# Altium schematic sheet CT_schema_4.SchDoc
size 398 x 262 mm
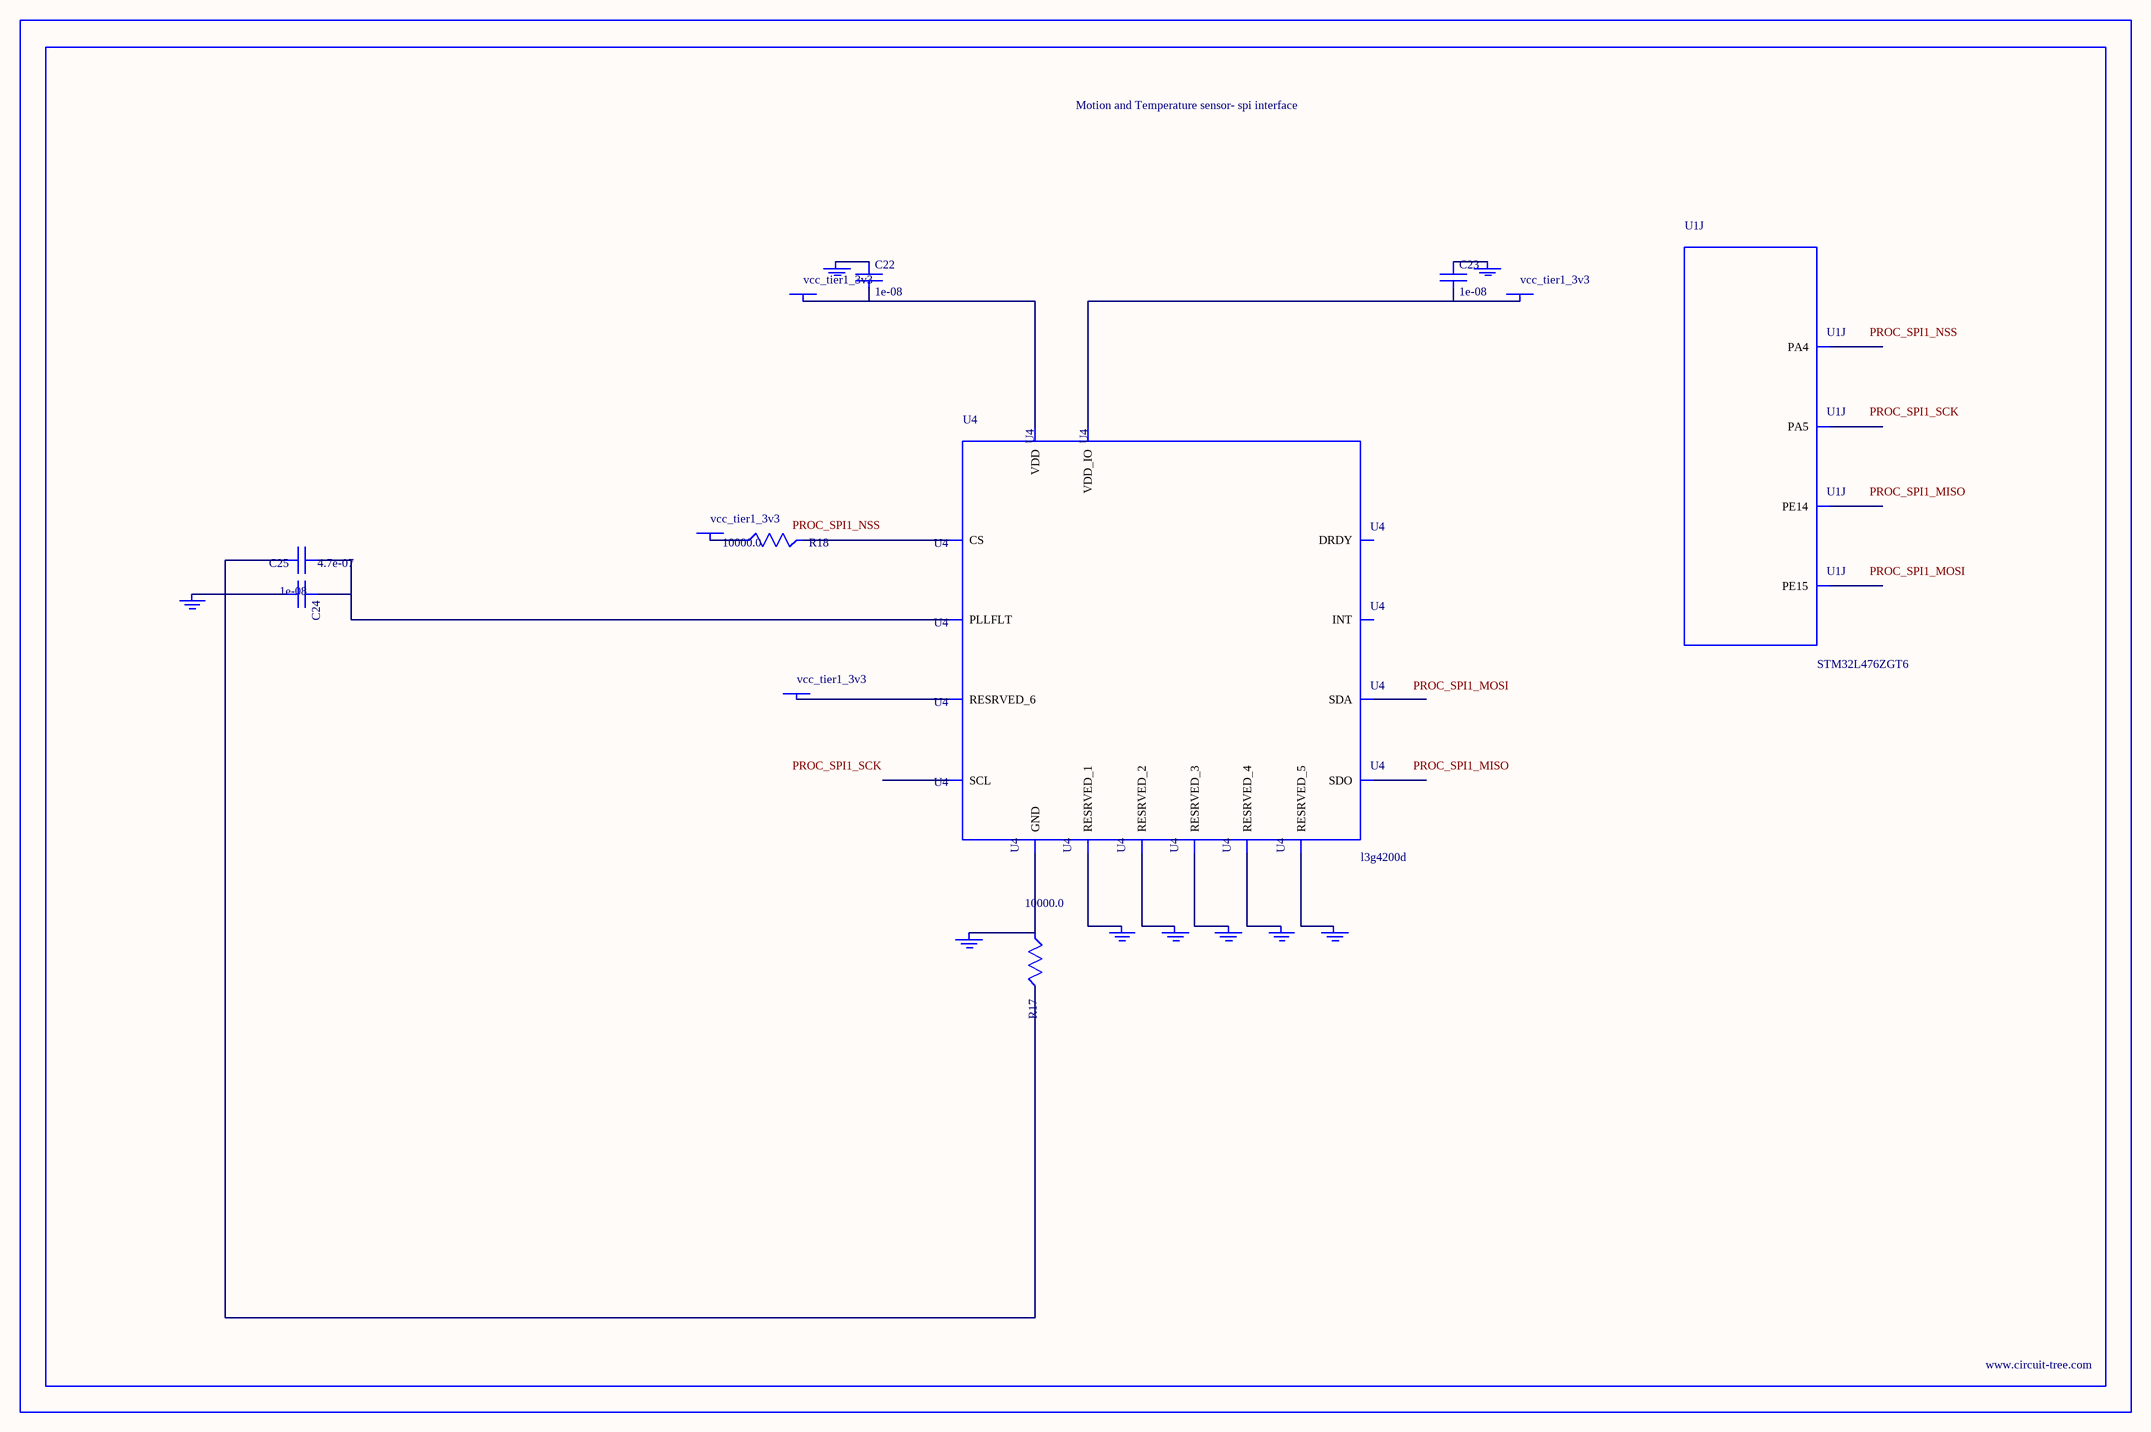
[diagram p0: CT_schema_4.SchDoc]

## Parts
BORDER3  (no value)
C22  1e-08  [C0402]
C23  1e-08  [C0402]
C24  1e-08  [C0402]
C25  4.7e-07  [C0603]
GND_INSTANCE_3_0  (no value)
GND_INSTANCE_3_1  (no value)
GND_INSTANCE_3_2  (no value)
GND_INSTANCE_3_3  (no value)
GND_INSTANCE_3_4  (no value)
GND_INSTANCE_3_5  (no value)
GND_INSTANCE_3_6  (no value)
GND_INSTANCE_3_7  (no value)
GND_INSTANCE_3_8  (no value)
POWER_INSTANCE_3_0  vcc_tier1_3v3
POWER_INSTANCE_3_1  vcc_tier1_3v3
POWER_INSTANCE_3_2  vcc_tier1_3v3
POWER_INSTANCE_3_3  vcc_tier1_3v3
R17  10000.0  [R0603]
R18  10000.0  [R0603]
U1  STM32L476ZGT6  [LQFP144]  (part J of 13)
U4  l3g4200d  [LGA-16]

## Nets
NetC22_1: C22.1 GND_INSTANCE_3_8.0(GND)
NetC22_2: C22.2 POWER_INSTANCE_3_3.0(PWR) U4.16(VDD)
NetC23_1: C23.1 GND_INSTANCE_3_0.0(GND)
NetC23_2: C23.2 POWER_INSTANCE_3_0.0(PWR) U4.1(VDD_IO)
NetC24_1: C24.1 C25.1 U4.14(PLLFLT)
NetC24_2: C24.2 C25.2 GND_INSTANCE_3_7.0(GND) R17.2
NetGND_INSTANCE_3_1_0: GND_INSTANCE_3_1.0(GND) U4.8(RESRVED_1)
NetGND_INSTANCE_3_2_0: GND_INSTANCE_3_2.0(GND) U4.9(RESRVED_2)
NetGND_INSTANCE_3_3_0: GND_INSTANCE_3_3.0(GND) U4.10(RESRVED_3)
NetGND_INSTANCE_3_4_0: GND_INSTANCE_3_4.0(GND) U4.11(RESRVED_4)
NetGND_INSTANCE_3_5_0: GND_INSTANCE_3_5.0(GND) U4.12(RESRVED_5)
NetGND_INSTANCE_3_6_0: GND_INSTANCE_3_6.0(GND) R17.1 U4.13(GND)
NetPOWER_INSTANCE_3_1_0: POWER_INSTANCE_3_1.0(PWR) R18.1
NetPOWER_INSTANCE_3_2_0: POWER_INSTANCE_3_2.0(PWR) U4.15(RESRVED_6)
NetR18_2: R18.2 U4.5(CS)

Not connected (* = marked no-connect by the designer): U1 40(PA4) 41(PA5) 67(PE14) 68(PE15); U4 2(SCL) 3(SDA) 4(SDO) 6(DRDY) 7(INT)

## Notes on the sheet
- Labels drawn without touching a wire or pin: PROC_SPI1_MISO, PROC_SPI1_MOSI, PROC_SPI1_NSS, PROC_SPI1_SCK

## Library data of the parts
BORDER3 = BORDER_PAGE3
C22-C24 = C0402C103K3RAC
C25 = C0603C474K3RAC
GND_INSTANCE_3_0-GND_INSTANCE_3_8 = GND
POWER_INSTANCE_3_0-POWER_INSTANCE_3_3 = PWR
R17 R18 = RC0603JR-0710KL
